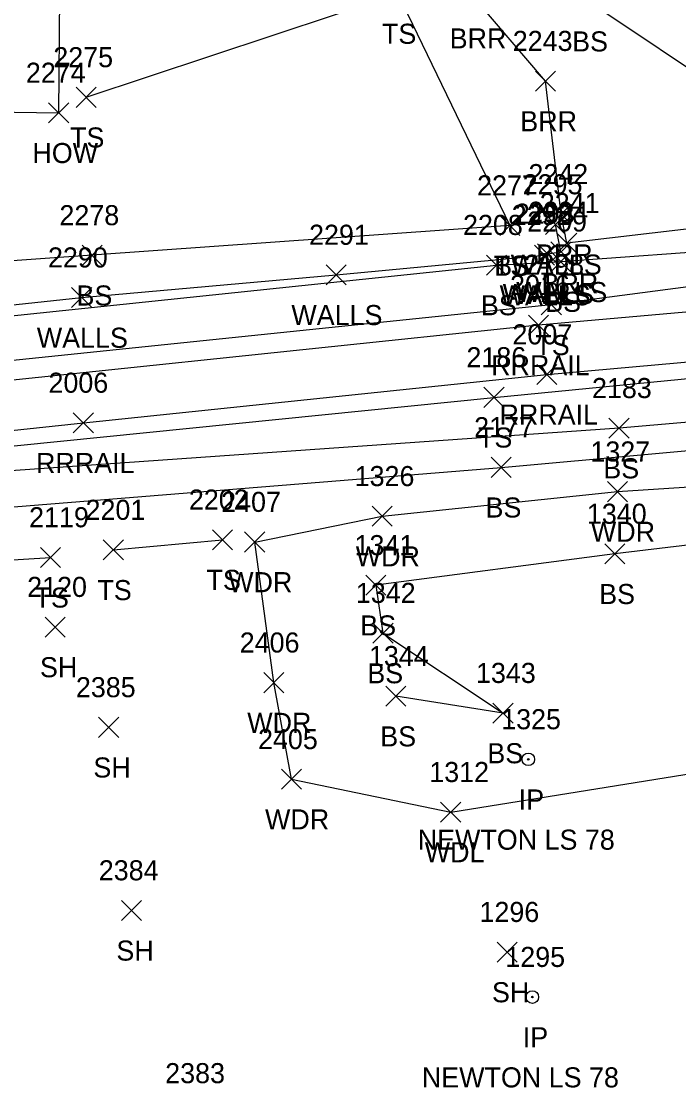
# Model space of a CAD drawing. Extents: x 1609623 to 1616187, y 756677 to 762826.
# Drawn here: x 1610666.8 to 1610732.2, y 761796.6 to 761902.8 of the extents above; entities that cross this region are included whole.
import ezdxf

# ---------------------------------------------------------------- set-up
doc = ezdxf.new("R2010")
doc.units = 0
for name, color, linetype in [('L_A', 7, 'Continuous'), ('L_I', 7, 'Continuous'), ('L_TIC', 7, 'Continuous'), ('LABL', 7, 'Continuous'), ('LAWA', 7, 'Continuous'), ('LBC', 7, 'Continuous'), ('LELB', 7, 'Continuous'), ('LWS', 7, 'Continuous'), ('M_A', 7, 'Continuous'), ('M_C', 7, 'Continuous'), ('M_I', 7, 'Continuous'), ('MPIR', 7, 'Continuous'), ('R_A', 7, 'Continuous'), ('R_I', 7, 'Continuous'), ('R_TIC', 7, 'Continuous'), ('RR', 7, 'Continuous')]:
    doc.layers.add(name, color=color, linetype=linetype)

msp = doc.modelspace()

# ---------------------------------------------------------------- linework, layer by layer
at = {"layer": 'L_TIC'}
for points in [[(1610717.95, 761895.88), (1610719.95, 761897.88)], [(1610719.95, 761895.88), (1610717.95, 761897.88)], [(1610672.21, 761894.26), (1610674.21, 761896.26)], [(1610674.21, 761894.26), (1610672.21, 761896.26)], [(1610669.48, 761892.71), (1610671.48, 761894.71)], [(1610671.48, 761892.71), (1610669.48, 761894.71)], [(1610719.51, 761882.61), (1610721.51, 761884.61)], [(1610721.51, 761882.61), (1610719.51, 761884.61)], [(1610714.4, 761881.49), (1610716.4, 761883.49)], [(1610716.4, 761881.49), (1610714.4, 761883.49)], [(1610714.4, 761881.49), (1610716.4, 761883.49)], [(1610716.4, 761881.49), (1610714.4, 761883.49)], [(1610718.94, 761881.6), (1610720.94, 761883.6)], [(1610720.94, 761881.6), (1610718.94, 761883.6)], [(1610720.08, 761879.72), (1610722.08, 761881.72)], [(1610722.08, 761879.72), (1610720.08, 761881.72)], [(1610672.82, 761878.52), (1610674.82, 761880.52)], [(1610674.82, 761878.52), (1610672.82, 761880.52)], [(1610717.84, 761878.54), (1610719.84, 761880.54)], [(1610719.84, 761878.54), (1610717.84, 761880.54)], [(1610718.15, 761878.67), (1610720.15, 761880.67)], [(1610720.15, 761878.67), (1610718.15, 761880.67)], [(1610719.49, 761878.86), (1610721.49, 761880.86)], [(1610721.49, 761878.86), (1610719.49, 761880.86)], [(1610713.08, 761877.55), (1610715.08, 761879.55)], [(1610715.08, 761877.55), (1610713.08, 761879.55)], [(1610719.48, 761877.89), (1610721.48, 761879.89)], [(1610721.48, 761877.89), (1610719.48, 761879.89)], [(1610697.11, 761876.57), (1610699.11, 761878.57)], [(1610699.11, 761876.57), (1610697.11, 761878.57)], [(1610671.77, 761874.31), (1610673.77, 761876.31)], [(1610673.77, 761874.31), (1610671.77, 761876.31)], [(1610718.53, 761873.58), (1610720.53, 761875.58)], [(1610720.53, 761873.58), (1610718.53, 761875.58)], [(1610712.82, 761864.37), (1610714.82, 761866.37)], [(1610714.82, 761864.37), (1610712.82, 761866.37)], [(1610725.27, 761861.3), (1610727.27, 761863.3)], [(1610727.27, 761861.3), (1610725.27, 761863.3)], [(1610713.54, 761857.4), (1610715.54, 761859.4)], [(1610715.54, 761857.4), (1610713.54, 761859.4)], [(1610725.11, 761854.98), (1610727.11, 761856.98)], [(1610727.11, 761854.98), (1610725.11, 761856.98)], [(1610701.7, 761852.53), (1610703.7, 761854.53)], [(1610703.7, 761852.53), (1610701.7, 761854.53)], [(1610685.79, 761850.19), (1610687.79, 761852.19)], [(1610687.79, 761850.19), (1610685.79, 761852.19)], [(1610689, 761849.96), (1610691, 761851.96)], [(1610691, 761849.96), (1610689, 761851.96)], [(1610674.93, 761849.17), (1610676.93, 761851.17)], [(1610676.93, 761849.17), (1610674.93, 761851.17)], [(1610724.85, 761848.78), (1610726.85, 761850.78)], [(1610726.85, 761848.78), (1610724.85, 761850.78)], [(1610668.67, 761848.43), (1610670.67, 761850.43)], [(1610670.67, 761848.43), (1610668.67, 761850.43)], [(1610701.07, 761845.65), (1610703.07, 761847.65)], [(1610703.07, 761845.65), (1610701.07, 761847.65)], [(1610669.13, 761841.49), (1610671.13, 761843.49)], [(1610671.13, 761841.49), (1610669.13, 761843.49)], [(1610701.77, 761840.89), (1610703.77, 761842.89)], [(1610703.77, 761840.89), (1610701.77, 761842.89)], [(1610690.9, 761835.95), (1610692.9, 761837.95)], [(1610692.9, 761835.95), (1610690.9, 761837.95)], [(1610703.06, 761834.6), (1610705.06, 761836.6)], [(1610705.06, 761834.6), (1610703.06, 761836.6)], [(1610713.72, 761832.92), (1610715.72, 761834.92)], [(1610715.72, 761832.92), (1610713.72, 761834.92)], [(1610674.46, 761831.5), (1610676.46, 761833.5)], [(1610676.46, 761831.5), (1610674.46, 761833.5)], [(1610692.67, 761826.33), (1610694.67, 761828.33)], [(1610694.67, 761826.33), (1610692.67, 761828.33)], [(1610708.51, 761823.05), (1610710.51, 761825.05)], [(1610710.51, 761823.05), (1610708.51, 761825.05)], [(1610676.74, 761813.26), (1610678.74, 761815.26)], [(1610678.74, 761813.26), (1610676.74, 761815.26)], [(1610714.13, 761809.11), (1610716.13, 761811.11)], [(1610716.13, 761809.11), (1610714.13, 761811.11)]]:
    msp.add_lwpolyline(points, dxfattribs=at)
at = {"layer": 'LABL'}
msp.add_lwpolyline([(1610822.8, 761990.5), (1610816.37, 761964.31), (1610799.33, 761934.51), (1610779.53, 761924.47), (1610770.7, 761892.35), (1610746.55, 761883.72), (1610721.08, 761880.72), (1610720.51, 761883.61), (1610718.95, 761896.88), (1610711.92, 761905.13), (1610716.12, 761931.04), (1610735.71, 761944.11), (1610756.54, 761960.66), (1610765.19, 761988.18), (1610792.34, 761999.44)], dxfattribs=at)
at = {"layer": 'LAWA'}
for points in [[(1610702.7, 761853.53), (1610726.11, 761855.98), (1610750.64, 761857.59), (1610801.13, 761860.13), (1610822.53, 761864.48), (1610864.79, 761868.85), (1610920.77, 761864.78)], [(1610690, 761850.96), (1610702.7, 761853.53)], [(1610693.67, 761827.33), (1610691.9, 761836.95), (1610690, 761850.96)], [(1610709.51, 761824.05), (1610738.59, 761828.73), (1610790.87, 761826.81), (1610812.47, 761811.74), (1610836.11, 761811.63), (1610862.21, 761818.34), (1610884.63, 761819.38), (1610912.68, 761817.87)], [(1610693.67, 761827.33), (1610709.51, 761824.05)]]:
    msp.add_lwpolyline(points, dxfattribs=at)
at = {"layer": 'LBC'}
for points in [[(1610670.49, 761964.48), (1610670.77, 761928.82), (1610670.48, 761893.71)], [(1610646.42, 761894.07), (1610670.48, 761893.71)]]:
    msp.add_lwpolyline(points, dxfattribs=at)
at = {"layer": 'LELB'}
for points in [[(1610797.68, 761989.86), (1610780.22, 761978.82), (1610784.28, 761960.78), (1610779.54, 761944.21), (1610758.52, 761925.28), (1610741.66, 761915.73), (1610737.46, 761895.28), (1610723.16, 761904.83), (1610726.7, 761921.62)], [(1610673.21, 761895.26), (1610704.26, 761905.59), (1610715.4, 761882.49)], [(1610602.02, 761864.56), (1610614.03, 761865.91), (1610622.79, 761867.09), (1610622.97, 761869.26), (1610659.73, 761872.87), (1610714.08, 761878.55), (1610720.48, 761878.89), (1610757.05, 761881.57), (1610797.88, 761885.85), (1610817.91, 761890.37)], [(1610921.86, 761880.14), (1610871.16, 761882.93), (1610826.32, 761885.02), (1610800.07, 761882.65), (1610757.14, 761879.52), (1610719.53, 761874.58), (1610660.79, 761868.5), (1610632.31, 761866)], [(1610715.4, 761882.49), (1610673.82, 761879.52), (1610652.76, 761878.03), (1610642.52, 761877.48), (1610635.27, 761881.7), (1610633.2, 761877.75), (1610631.31, 761872.33)], [(1610662.06, 761860.15), (1610713.82, 761865.37), (1610758.9, 761869.76), (1610806.76, 761872.59), (1610826.23, 761873.47), (1610870.39, 761874.23), (1610922.11, 761870.11)], [(1610663.1, 761854.24), (1610714.54, 761858.4), (1610758.81, 761862.41), (1610802.48, 761864.96), (1610818.8, 761865.65), (1610799.52, 761868.01), (1610758.49, 761865.08), (1610726.27, 761862.3), (1610662.37, 761857.81)], [(1610915.2, 761848.72), (1610887.85, 761842.06), (1610865.29, 761840.84), (1610840.62, 761842.15), (1610818.45, 761850.99), (1610797.84, 761857.01), (1610749.75, 761852.65), (1610725.85, 761849.78), (1610702.07, 761846.65), (1610702.77, 761841.89), (1610714.72, 761833.92), (1610704.06, 761835.6)], [(1610675.93, 761850.17), (1610686.79, 761851.19)], [(1610630.24, 761842.76), (1610642.68, 761845.4), (1610656.2, 761848.59), (1610669.67, 761849.43)]]:
    msp.add_lwpolyline(points, dxfattribs=at)
at = {"layer": 'LWS'}
msp.add_lwpolyline([(1610623.07, 761870.78), (1610631.16, 761871.52), (1610658.78, 761873.84), (1610672.77, 761875.31), (1610698.11, 761877.57), (1610718.84, 761879.54), (1610719.15, 761879.67), (1610720.49, 761879.86), (1610719.94, 761882.6)], dxfattribs=at)
at = {"layer": 'MPIR'}
for centre, radius in [((1610717.24, 761829.31), 0.625), ((1610717.24, 761829.31), 0.0833), ((1610717.64, 761805.63), 0.625), ((1610717.64, 761805.63), 0.0833)]:
    msp.add_circle(centre, radius, dxfattribs=at)
at = {"layer": 'R_TIC'}
for points in [[(1610717.25, 761871.56), (1610719.25, 761873.56)], [(1610719.25, 761871.56), (1610717.25, 761873.56)], [(1610718.08, 761866.65), (1610720.08, 761868.65)], [(1610720.08, 761866.65), (1610718.08, 761868.65)], [(1610671.94, 761861.83), (1610673.94, 761863.83)], [(1610673.94, 761861.83), (1610671.94, 761863.83)]]:
    msp.add_lwpolyline(points, dxfattribs=at)
at = {"layer": 'RR'}
for points in [[(1610920.34, 761877.5), (1610875.2, 761880.63), (1610823.88, 761880.35), (1610770.14, 761877.16), (1610718.25, 761872.56), (1610624.39, 761862.75), (1610528.95, 761852.85), (1610433.45, 761843.38), (1610390.08, 761839.1), (1610343.15, 761834.31), (1610326.86, 761832.49), (1610295.2, 761829.73), (1610250.28, 761826.15), (1610201.81, 761823.95), (1610155.3, 761823.62), (1610106.26, 761824.63), (1610057.65, 761827.02), (1610007.52, 761831.91), (1609961.32, 761837.48), (1609915.47, 761844.69), (1609871.57, 761853.1), (1609828.18, 761862.73), (1609811.27, 761866.9)], [(1609812.23, 761861.59), (1609849.51, 761852.68), (1609889.11, 761844.53), (1609934.67, 761836.61), (1609980.82, 761829.97), (1610026.24, 761824.91), (1610071.82, 761821.22), (1610118.39, 761819.39), (1610165.38, 761818.61), (1610213.1, 761819.4), (1610261.76, 761821.96), (1610309.94, 761826.07), (1610356.6, 761830.72), (1610389.15, 761834), (1610434.7, 761838.51), (1610480.7, 761843.13), (1610575.97, 761852.51), (1610672.94, 761862.83), (1610719.08, 761867.65), (1610767.25, 761871.97), (1610815.87, 761875.05), (1610864.69, 761875.82), (1610894.81, 761874.78)]]:
    msp.add_lwpolyline(points, dxfattribs=at)

# ---------------------------------------------------------------- texts
at = {"layer": 'L_A'}
for s, p in [('TS', (1610702.67, 761900.59)), ('BRR', (1610709.41, 761900.13)), ('BS', (1610721.6, 761899.83)), ('BRR', (1610716.44, 761891.88)), ('TS', (1610671.62, 761890.26)), ('HOW', (1610667.87, 761888.71)), ('BRR', (1610718, 761878.61)), ('TS', (1610713.81, 761877.49)), ('BS', (1610713.84, 761877.49)), ('WALLS', (1610715.48, 761877.6)), ('BRR', (1610718.56, 761875.72)), ('BS', (1610672.26, 761874.52)), ('WALLS', (1610714.38, 761874.54)), ('WALLS', (1610714.69, 761874.67)), ('WALLS', (1610716.03, 761874.86)), ('BS', (1610712.52, 761873.55)), ('BS', (1610718.92, 761873.89)), ('WALLS', (1610693.65, 761872.57)), ('WALLS', (1610668.31, 761870.31)), ('TS', (1610717.94, 761869.58)), ('TS', (1610712.23, 761860.37)), ('BS', (1610724.71, 761857.3)), ('BS', (1610712.98, 761853.4)), ('WDR', (1610723.47, 761850.98)), ('WDR', (1610700.06, 761848.53)), ('TS', (1610685.2, 761846.19)), ('WDR', (1610687.36, 761845.96)), ('TS', (1610668.08, 761844.43)), ('TS', (1610674.34, 761845.17)), ('BS', (1610724.29, 761844.78)), ('BS', (1610700.51, 761841.65)), ('SH', (1610668.62, 761837.49)), ('BS', (1610701.21, 761836.89)), ('WDR', (1610689.26, 761831.95)), ('BS', (1610702.5, 761830.6)), ('BS', (1610713.16, 761828.92)), ('SH', (1610673.94, 761827.5)), ('WDR', (1610691.03, 761822.33)), ('WDL', (1610706.93, 761819.05)), ('SH', (1610676.23, 761809.26)), ('SH', (1610713.62, 761805.11))]:
    msp.add_text(s, height=2, dxfattribs=at).set_placement(p)
at = {"layer": 'L_I'}
for s, p in [('2243', (1610715.69, 761899.88)), ('2275', (1610669.95, 761898.26)), ('2274', (1610667.22, 761896.71)), ('2242', (1610717.25, 761886.61)), ('2277', (1610712.14, 761885.49)), ('2277', (1610712.14, 761885.49)), ('2295', (1610716.68, 761885.6)), ('2241', (1610718.38, 761883.72)), ('2278', (1610670.56, 761882.52)), ('2292', (1610715.58, 761882.54)), ('2293', (1610715.89, 761882.67)), ('2294', (1610717.23, 761882.86)), ('2208', (1610710.74, 761881.55)), ('2209', (1610717.13, 761881.89)), ('2291', (1610695.41, 761880.57)), ('2290', (1610669.42, 761878.31)), ('2198', (1610716.84, 761877.58)), ('2186', (1610711.08, 761868.37)), ('2183', (1610723.58, 761865.3)), ('2177', (1610711.85, 761861.4)), ('1327', (1610723.42, 761858.98)), ('1326', (1610699.95, 761856.53)), ('2202', (1610683.45, 761854.19)), ('2407', (1610686.66, 761853.96)), ('2201', (1610673.16, 761853.17)), ('1340', (1610723.07, 761852.78)), ('2119', (1610667.54, 761852.43)), ('1341', (1610699.94, 761849.65)), ('2120', (1610667.35, 761845.49)), ('1342', (1610700.07, 761844.89)), ('2406', (1610688.51, 761839.95)), ('1344', (1610701.37, 761838.6)), ('1343', (1610712.03, 761836.92)), ('2385', (1610672.2, 761835.5)), ('2405', (1610690.33, 761830.33)), ('1312', (1610707.38, 761827.05)), ('2384', (1610674.48, 761817.26)), ('1296', (1610712.38, 761813.11)), ('2383', (1610681.09, 761797.05))]:
    msp.add_text(s, height=2, dxfattribs=at).set_placement(p)
at = {"layer": 'M_A'}
for p in [(1610716.28, 761824.31), (1610716.69, 761800.63)]:
    msp.add_text('IP', height=2, dxfattribs=at).set_placement(p)
at = {"layer": 'M_C'}
for p in [(1610706.23, 761820.31), (1610706.64, 761796.63)]:
    msp.add_text('NEWTON LS 78', height=2, dxfattribs=at).set_placement(p)
at = {"layer": 'M_I'}
for s, p in [('1325', (1610714.54, 761832.31)), ('1295', (1610714.95, 761808.63))]:
    msp.add_text(s, height=2, dxfattribs=at).set_placement(p)
at = {"layer": 'R_A'}
for p in [(1610713.54, 761867.56), (1610714.37, 761862.65), (1610668.23, 761857.83)]:
    msp.add_text('RRRAIL', height=2, dxfattribs=at).set_placement(p)
at = {"layer": 'R_I'}
for s, p in [('2016', (1610715.42, 761875.56)), ('2007', (1610715.66, 761870.65)), ('2006', (1610669.47, 761865.83))]:
    msp.add_text(s, height=2, dxfattribs=at).set_placement(p)

doc.saveas('drawing.dxf')
